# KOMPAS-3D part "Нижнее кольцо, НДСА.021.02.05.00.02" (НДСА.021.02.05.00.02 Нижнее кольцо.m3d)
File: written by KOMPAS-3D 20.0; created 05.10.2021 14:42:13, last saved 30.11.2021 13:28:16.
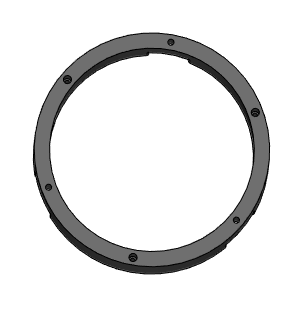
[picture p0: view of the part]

Document properties: Полное имя файла: C:\Users\korychko\Desktop\PLM\НДСА.021.02.05.00.02 Нижнее кольцо.m3d

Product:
- Part/product: Нижнее кольцо  | designation НДСА.021.02.05.00.02
    Материал: Д16  ГОСТ 4784-2019 (density 2800 kg/m3)
    Масса: 3.75156
    additional columns: <item xmlns="http://appius.ru/pdm" xmlns:xs="http://www.w3.org/2001/XMLSchema" x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; <item xmlns="http://appius.ru/pdm" xmlns:xs="http://www.w3.org/2001/XMLSchema" x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; <item xmlns="http://appius.ru/pdm" xmlns:xs="http://www.w3.org/2001/XMLSchema" x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
    source file: НДСА.021.02.05.00.02 Нижнее кольцо.cdw

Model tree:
1. Эскиз:1
2. Элемент выдавливания:1
     Расстояние 1 = 81
3. Эскиз:2  (with: Элемент выдавливания:1)
4. Элемент выдавливания:2
     Расстояние 2 = 81
5. Массив по концентрической сетке:1  (with: Элемент выдавливания:2)  (3 pattern instances)
     Шаг 2 = 360
6. Эскиз:3  (with: Элемент выдавливания:1, Элемент выдавливания:2)
7. Элемент выдавливания:3
     Расстояние 2 = 34
8. Массив по концентрической сетке:2  (with: Элемент выдавливания:3)  (3 pattern instances)
     Шаг 2 = 360
9. Условное изображение резьбы:1  (with: Элемент выдавливания:2)  (labels: M10; cil0_24705-2004 coarse)
     Длина резьбы = 81; Шаг резьбы = 1.5; Номинальный диаметр резьбы = 10
10. Подгонка:1  (with: Элемент выдавливания:2)
11. Условное изображение резьбы:2  (with: Элемент выдавливания:2)  (labels: M10; cil0_24705-2004 coarse)
     Длина резьбы = 81; Шаг резьбы = 1.5; Номинальный диаметр резьбы = 10
12. Подгонка:2  (with: Элемент выдавливания:2)
13. Условное изображение резьбы:3  (with: Элемент выдавливания:2)  (labels: M10; cil0_24705-2004 coarse)
     Длина резьбы = 81; Шаг резьбы = 1.5; Номинальный диаметр резьбы = 10
14. Подгонка:3  (with: Элемент выдавливания:2)
15. Эскиз:4  (with: Элемент выдавливания:1, Элемент выдавливания:2)
16. Элемент выдавливания:4
     Расстояние 1 = 31
17. Массив по концентрической сетке:3  (with: Элемент выдавливания:4, Элемент выдавливания:1)  (3 pattern instances)
     Шаг 2 = 360
18. Скругление:1  (with: Элемент выдавливания:4)  (labels: Д16  ГОСТ 4784-2019)
     Радиус = 3

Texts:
  НДСА.021.02.05.00.02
